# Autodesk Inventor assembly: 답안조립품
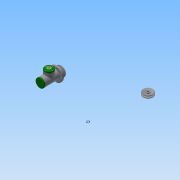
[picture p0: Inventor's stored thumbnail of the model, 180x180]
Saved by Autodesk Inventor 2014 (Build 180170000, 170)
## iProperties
Created: 2016-08
Part Number: 답안조립품
Document SubType Name: Assembly
Designer: net
Author: net
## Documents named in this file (25)
- C:\Users\net\Desktop\460807V1023\답안조립품.iam
- C:\Users\net\Desktop\460807V1023\답안본체.ipt
- C:\Users\net\Desktop\460807V1023\V-벨트풀리.ipt
- C:\Users\net\Desktop\460807V1023\너트 M10.ipt
- C:\Users\net\Desktop\460807V1023\링크.ipt
- C:\Users\net\Desktop\460807V1023\멈춤링 15 x 1.ipt
- C:\Users\net\Desktop\460807V1023\멈춤링 35x1.6.ipt
- C:\Users\net\Desktop\460807V1023\베어링 15 x 35 x 11.ipt
- C:\Users\net\Desktop\460807V1023\볼트 M4 x 10.ipt
- C:\Users\net\Desktop\460807V1023\볼트 M4 x 12.ipt
- C:\Users\net\Desktop\460807V1023\부시1.ipt
- C:\Users\net\Desktop\460807V1023\부시2.ipt
- C:\Users\net\Desktop\460807V1023\분할핀 1.6 x 12.ipt
- C:\Users\net\Desktop\460807V1023\사이드 커버.ipt
- 사이드 커버.ipt
- C:\Users\net\Desktop\460807V1023\슬라이더.ipt
- C:\Users\net\Desktop\460807V1023\오일 실 15 25 7.ipt
- C:\Users\net\Desktop\460807V1023\와셔 4x16.ipt
- C:\Users\net\Desktop\460807V1023\와셔 10x21.ipt
- C:\Users\net\Desktop\460807V1023\클래스터 핀 6 x 24.ipt
- C:\Users\net\Desktop\460807V1023\키 4 x 4 x 18.ipt
- C:\Users\net\Desktop\460807V1023\탑 부시.ipt
- C:\Users\net\Desktop\460807V1023\탑 커버.ipt
- 탑 커버.ipt
- C:\Users\net\Desktop\460807V1023\편심축.ipt
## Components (7 placed, 3 different names)
1. V-벨트풀리:1
2. ISO 4017 M4 x 10:1
3. V-벨트풀리:2 — 각도:1
4. ISO 4762 M4 x 12:1
5. ISO 4762 M4 x 12:2
6. ISO 4762 M4 x 12:3
7. ISO 4762 M4 x 12:4
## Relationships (1: Angle 1)
- 각도:1 [Angle]: V-벨트풀리:2
